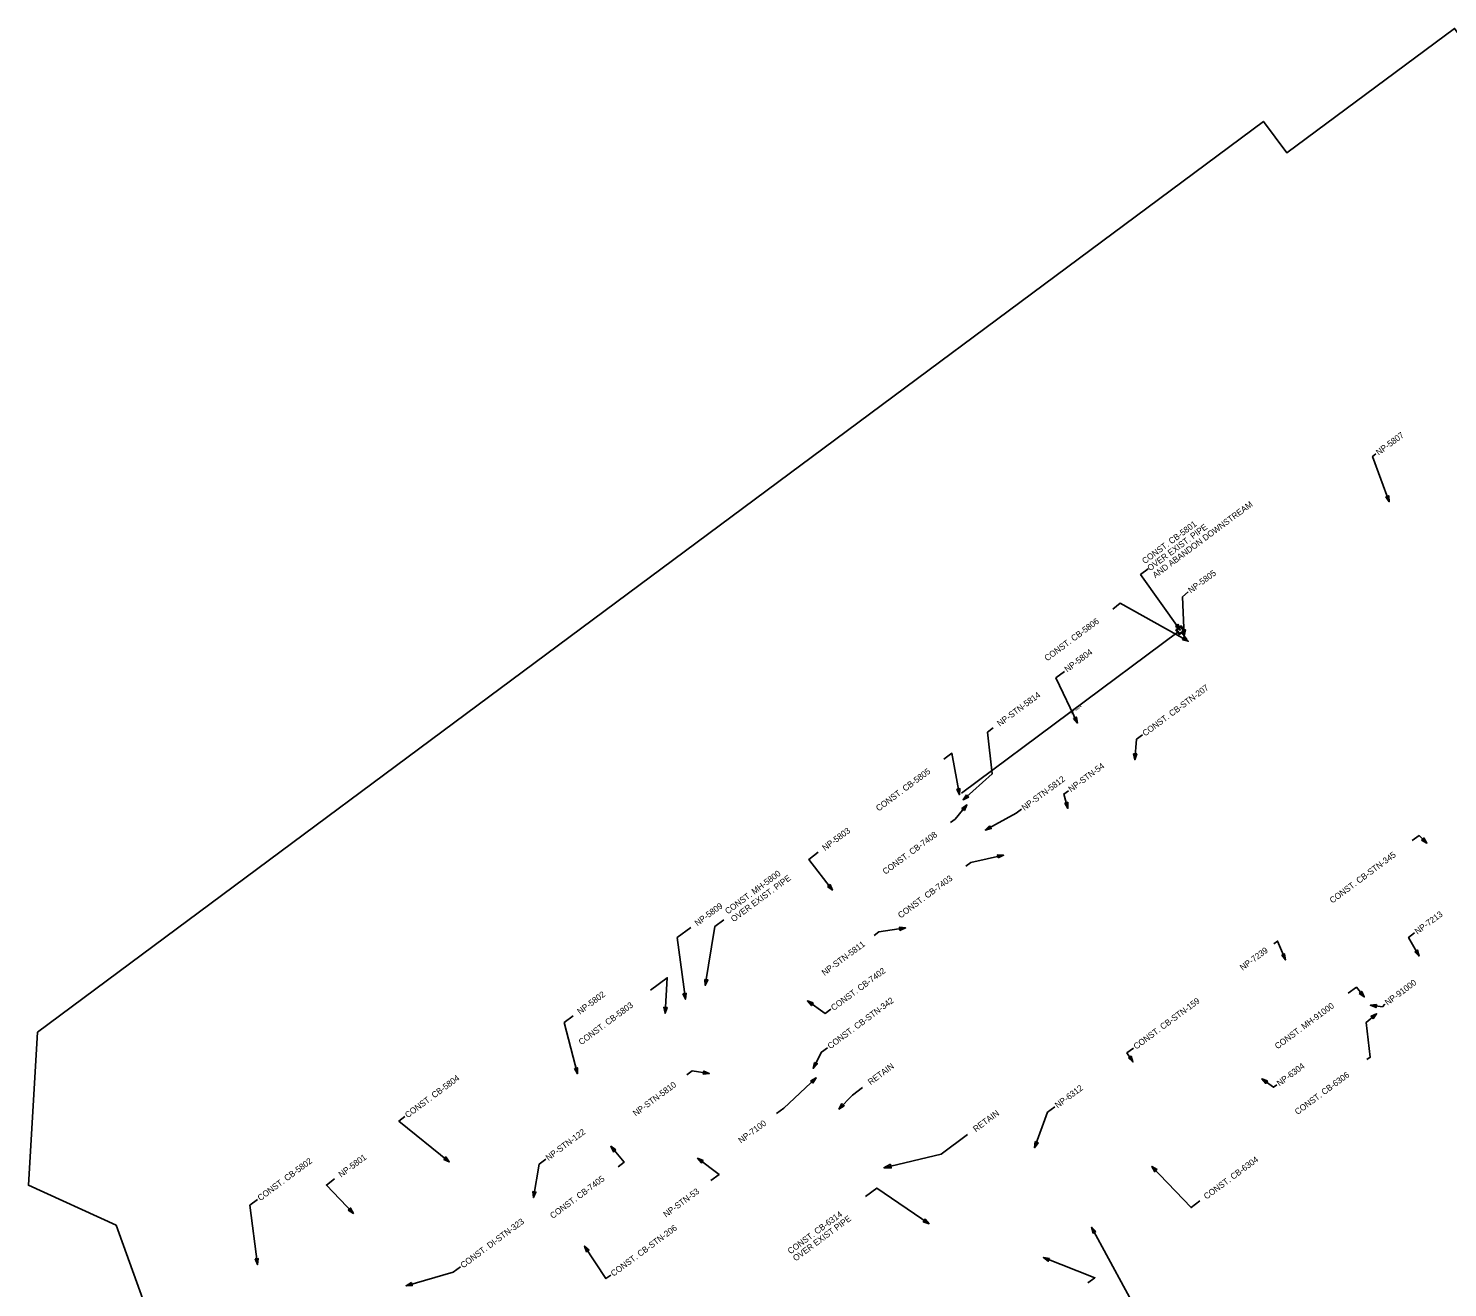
# Model space of a CAD drawing. Extents: x 1611197 to 1612945, y 1093889 to 1095652.
# Drawn here: x 1611197 to 1612358, y 1094591 to 1095622 of the extents above; entities that cross this region are included whole.
import ezdxf

# ---------------------------------------------------------------- set-up
doc = ezdxf.new("R2010")
doc.units = 0
for name, color, linetype in [('Default', 7, 'Continuous'), ('Plan_Clip', 7, 'Continuous'), ('RD_PD_DR_Inlet', 7, 'Continuous'), ('RD_PD_DR_Pipe', 7, 'Continuous'), ('RD_TX_Drainage', 7, 'Continuous')]:
    doc.layers.add(name, color=color, linetype=linetype)

msp = doc.modelspace()

# ---------------------------------------------------------------- linework, layer by layer
at = {"layer": 'Plan_Clip'}
msp.add_lwpolyline([(1611268.7, 1094642.2), (1611330.5, 1094471.1), (1611497.9, 1094245.9), (1611487.3, 1094233.1), (1611570.5, 1094184.4), (1611553.7, 1094158.9), (1611675.8, 1094087.5), (1611739.8, 1094059.2), (1612815.4, 1094815.5), (1612742.5, 1095078.7), (1612653.4, 1095198.5), (1612656.9, 1095201.1), (1612580.2, 1095304.3), (1612588.4, 1095320.1), (1612485.6, 1095458.4), (1612364.1, 1095621.9), (1612226.9, 1095519.9), (1612207.6, 1095545.8), (1611204.4, 1094800.1), (1611197, 1094674.8)], close=True, dxfattribs=at)
msp.add_lwpolyline([(1611268.7, 1094642.2), (1611330.5, 1094471.1), (1611497.9, 1094245.9), (1611487.3, 1094233.1), (1611570.5, 1094184.4), (1611553.7, 1094158.9), (1611675.8, 1094087.5), (1611739.8, 1094059.2), (1612815.4, 1094815.5), (1612742.5, 1095078.7), (1612653.4, 1095198.5), (1612656.9, 1095201.1), (1612580.2, 1095304.3), (1612588.4, 1095320.1), (1612485.6, 1095458.4), (1612364.1, 1095621.9), (1612226.9, 1095519.9), (1612207.6, 1095545.8), (1611204.4, 1094800.1), (1611197, 1094674.8)], close=True, dxfattribs=at)
msp.add_lwpolyline([(1611268.7, 1094642.2), (1611330.5, 1094471.1), (1611497.9, 1094245.9), (1611487.3, 1094233.1), (1611570.5, 1094184.4), (1611553.7, 1094158.9), (1611675.8, 1094087.5), (1611739.8, 1094059.2), (1612815.4, 1094815.5), (1612742.5, 1095078.7), (1612653.4, 1095198.5), (1612656.9, 1095201.1), (1612580.2, 1095304.3), (1612588.4, 1095320.1), (1612485.6, 1095458.4), (1612364.1, 1095621.9), (1612226.9, 1095519.9), (1612207.6, 1095545.8), (1611204.4, 1094800.1), (1611197, 1094674.8)], close=True, dxfattribs=at)
msp.add_lwpolyline([(1611268.7, 1094642.2), (1611330.5, 1094471.1), (1611497.9, 1094245.9), (1611487.3, 1094233.1), (1611570.5, 1094184.4), (1611553.7, 1094158.9), (1611675.8, 1094087.5), (1611739.8, 1094059.2), (1612815.4, 1094815.5), (1612742.5, 1095078.7), (1612653.4, 1095198.5), (1612656.9, 1095201.1), (1612580.2, 1095304.3), (1612588.4, 1095320.1), (1612485.6, 1095458.4), (1612364.1, 1095621.9), (1612226.9, 1095519.9), (1612207.6, 1095545.8), (1611204.4, 1094800.1), (1611197, 1094674.8)], close=True, dxfattribs=at)
msp.add_lwpolyline([(1611268.7, 1094642.2), (1611330.5, 1094471.1), (1611497.9, 1094245.9), (1611487.3, 1094233.1), (1611570.5, 1094184.4), (1611553.7, 1094158.9), (1611675.8, 1094087.5), (1611739.8, 1094059.2), (1612815.4, 1094815.5), (1612742.5, 1095078.7), (1612653.4, 1095198.5), (1612656.9, 1095201.1), (1612580.2, 1095304.3), (1612588.4, 1095320.1), (1612485.6, 1095458.4), (1612364.1, 1095621.9), (1612226.9, 1095519.9), (1612207.6, 1095545.8), (1611204.4, 1094800.1), (1611197, 1094674.8)], close=True, dxfattribs=at)
msp.add_lwpolyline([(1611268.7, 1094642.2), (1611330.5, 1094471.1), (1611497.9, 1094245.9), (1611487.3, 1094233.1), (1611570.5, 1094184.4), (1611553.7, 1094158.9), (1611675.8, 1094087.5), (1611739.8, 1094059.2), (1612815.4, 1094815.5), (1612742.5, 1095078.7), (1612653.4, 1095198.5), (1612656.9, 1095201.1), (1612580.2, 1095304.3), (1612588.4, 1095320.1), (1612485.6, 1095458.4), (1612364.1, 1095621.9), (1612226.9, 1095519.9), (1612207.6, 1095545.8), (1611204.4, 1094800.1), (1611197, 1094674.8)], close=True, dxfattribs=at)
msp.add_lwpolyline([(1611268.7, 1094642.2), (1611330.5, 1094471.1), (1611497.9, 1094245.9), (1611487.3, 1094233.1), (1611570.5, 1094184.4), (1611553.7, 1094158.9), (1611675.8, 1094087.5), (1611739.8, 1094059.2), (1612815.4, 1094815.5), (1612742.5, 1095078.7), (1612653.4, 1095198.5), (1612656.9, 1095201.1), (1612580.2, 1095304.3), (1612588.4, 1095320.1), (1612485.6, 1095458.4), (1612364.1, 1095621.9), (1612226.9, 1095519.9), (1612207.6, 1095545.8), (1611204.4, 1094800.1), (1611197, 1094674.8)], close=True, dxfattribs=at)
msp.add_lwpolyline([(1611268.7, 1094642.2), (1611330.5, 1094471.1), (1611497.9, 1094245.9), (1611487.3, 1094233.1), (1611570.5, 1094184.4), (1611553.7, 1094158.9), (1611675.8, 1094087.5), (1611739.8, 1094059.2), (1612815.4, 1094815.5), (1612742.5, 1095078.7), (1612653.4, 1095198.5), (1612656.9, 1095201.1), (1612580.2, 1095304.3), (1612588.4, 1095320.1), (1612485.6, 1095458.4), (1612364.1, 1095621.9), (1612226.9, 1095519.9), (1612207.6, 1095545.8), (1611204.4, 1094800.1), (1611197, 1094674.8)], close=True, dxfattribs=at)
at = {"layer": 'RD_PD_DR_Inlet'}
for p, q in [((1612137.9, 1095128), (1612137.9, 1095128)), ((1612138.3, 1095130.8), (1612138.3, 1095130.8)), ((1612138.3, 1095130.8), (1612138.3, 1095130.8)), ((1612139.5, 1095129.2), (1612139.5, 1095129.2)), ((1612139.5, 1095129.2), (1612139.5, 1095129.2)), ((1612140.7, 1095127.6), (1612140.7, 1095127.6)), ((1612140.7, 1095127.6), (1612140.7, 1095127.6)), ((1612141.1, 1095130.4), (1612141.1, 1095130.4))]:
    msp.add_line(p, q, dxfattribs=at)
for points in [[(1612135.9, 1095129.6), (1612138.8, 1095125.6), (1612143.2, 1095128.8), (1612140.2, 1095132.8)], [(1612140, 1095132), (1612136.7, 1095129.6), (1612139.1, 1095126.4), (1612142.3, 1095128.8)]]:
    msp.add_lwpolyline(points, close=True, dxfattribs=at)
at = {"layer": 'RD_PD_DR_Pipe'}
for p, q in [((1611960.5, 1094995.7), (1612137.9, 1095128)), ((1612140.7, 1095127.6), (1612145, 1095121.7))]:
    msp.add_line(p, q, dxfattribs=at)
at = {"layer": 'RD_TX_Drainage'}
for points in [[(1612299.7, 1095273.5), (1612297, 1095271.5), (1612310.6, 1095234.3)], [(1612113.4, 1095179.4), (1612107.1, 1095174.7), (1612139.5, 1095129.2)], [(1612146, 1095160.6), (1612141.5, 1095156.6), (1612142.8, 1095124.6)], [(1612084.3, 1095146.5), (1612090.5, 1095151.2), (1612146.1, 1095120.1)], [(1612044.9, 1095095.4), (1612037.9, 1095090.2), (1612055.5, 1095053.2)], [(1611986.5, 1095049.2), (1611981.9, 1095045.7), (1611985.7, 1095011.5), (1611961.9, 1094990.4)], [(1612108.6, 1095043.5), (1612103.8, 1095039.9), (1612102.3, 1095023.2)], [(1611946.2, 1095023.5), (1611952.7, 1095028.4), (1611958.9, 1094994.5)], [(1612048, 1094997.8), (1612044.3, 1094995), (1612047.6, 1094983.3)], [(1611951.7, 1094971.8), (1611955.4, 1094974.5), (1611965, 1094986.2)], [(1612009.8, 1094982.7), (1612005.3, 1094979.3), (1611980, 1094965.6)], [(1612329.4, 1094957), (1612335, 1094961.1), (1612341.5, 1094954.9)], [(1611843.4, 1094947.4), (1611835.7, 1094941.6), (1611854.9, 1094916.4)], [(1611964.2, 1094935.9), (1611968.3, 1094938.9), (1611995, 1094945)], [(1611766.2, 1094892.2), (1611758.8, 1094886.7), (1611750.9, 1094838.4)], [(1611739, 1094885.7), (1611728, 1094877.5), (1611734.6, 1094827)], [(1611889, 1094879.3), (1611892.9, 1094882.2), (1611914.8, 1094885.4)], [(1612331.4, 1094881.3), (1612326.4, 1094877.7), (1612335, 1094862.4)], [(1612216.2, 1094872.4), (1612219.2, 1094874.7), (1612225.6, 1094859.3)], [(1611706.1, 1094834.5), (1611719.8, 1094844.6), (1611718, 1094815.6)], [(1612276.9, 1094831.9), (1612283.7, 1094836.9), (1612290.1, 1094828.9)], [(1611853.7, 1094818.9), (1611849, 1094815.4), (1611834.5, 1094825.7)], [(1612307, 1094823.1), (1612305, 1094820.8), (1612295.2, 1094822.2)], [(1611642.9, 1094813.4), (1611635.5, 1094807.9), (1611646.2, 1094766)], [(1612292.4, 1094777.6), (1612295.1, 1094779.6), (1612291.8, 1094808.1), (1612300.3, 1094815.2)], [(1611850.9, 1094787.4), (1611846, 1094783.8), (1611839.3, 1094770.4)], [(1612101.3, 1094787.1), (1612096, 1094783.1), (1612100.9, 1094775.7)], [(1611735.8, 1094765.2), (1611740.2, 1094768.5), (1611754.1, 1094766.2)], [(1611809.2, 1094733.5), (1611815.2, 1094738), (1611841.7, 1094762.6)], [(1611879.6, 1094754.7), (1611871.3, 1094748.6), (1611860.3, 1094737.2)], [(1612218.5, 1094757), (1612215.9, 1094755), (1612206.4, 1094762)], [(1611505.1, 1094731), (1611500.2, 1094727.3), (1611541.4, 1094693.9)], [(1612037, 1094739), (1612030.9, 1094734.5), (1612020.4, 1094705.5)], [(1611679.5, 1094689.9), (1611684.5, 1094693.6), (1611673.7, 1094706.7)], [(1611965.6, 1094716.2), (1611943.9, 1094700.1), (1611897.1, 1094689.1)], [(1611620.3, 1094696), (1611615, 1094692.1), (1611610.2, 1094664.7)], [(1611755.5, 1094678.6), (1611762.2, 1094683.5), (1611744.6, 1094696.9)], [(1612155.6, 1094661.9), (1612148.4, 1094656.5), (1612116.4, 1094690.2)], [(1611447.5, 1094679.9), (1611440.9, 1094674.9), (1611463, 1094651.7)], [(1611882, 1094665.5), (1611891.3, 1094672.4), (1611934, 1094643.3)], [(1611384.5, 1094663.1), (1611378.3, 1094658.4), (1611384.5, 1094609.8)], [(1612096.1, 1094554.2), (1612108.7, 1094563.6), (1612067, 1094640.4)], [(1611673.5, 1094601.2), (1611669.6, 1094598.3), (1611652.1, 1094625)], [(1612064, 1094594.8), (1612069.8, 1094599.1), (1612027.6, 1094615.5)], [(1611550.5, 1094608), (1611544.7, 1094603.7), (1611506.1, 1094592.5)]]:
    msp.add_lwpolyline(points, dxfattribs=at)
for points in [[(1612307.8, 1095238.4), (1612310.6, 1095234.3), (1612310.2, 1095239.3)], [(1612135.7, 1095132.4), (1612139.5, 1095129.2), (1612137.8, 1095133.9)], [(1612141.3, 1095129.4), (1612142.8, 1095124.6), (1612143.9, 1095129.5)], [(1612141.3, 1095121.3), (1612146.1, 1095120.1), (1612142.5, 1095123.6)], [(1612052.3, 1095057), (1612055.5, 1095053.2), (1612054.6, 1095058.1)], [(1612101.4, 1095028.1), (1612102.3, 1095023.2), (1612104, 1095027.9)], [(1611956.7, 1094999), (1611958.9, 1094994.5), (1611959.3, 1094999.5)], [(1611962.9, 1094981.7), (1611965, 1094986.2), (1611960.9, 1094983.3)], [(1611964.7, 1094994.5), (1611961.9, 1094990.4), (1611966.4, 1094992.6)], [(1612045, 1094987.6), (1612047.6, 1094983.3), (1612047.5, 1094988.3)], [(1611983.6, 1094969.1), (1611980, 1094965.6), (1611984.9, 1094966.8)], [(1612337.1, 1094957.3), (1612341.5, 1094954.9), (1612338.9, 1094959.2)], [(1611990.6, 1094942.7), (1611995, 1094945), (1611990, 1094945.2)], [(1611850.9, 1094919.5), (1611854.9, 1094916.4), (1611853, 1094921)], [(1611910.2, 1094883.4), (1611914.8, 1094885.4), (1611909.8, 1094886)], [(1612331.5, 1094866), (1612335, 1094862.4), (1612333.7, 1094867.3)], [(1612222.6, 1094863.2), (1612225.6, 1094859.3), (1612225, 1094864.2)], [(1611750.4, 1094843.3), (1611750.9, 1094838.4), (1611753, 1094842.9)], [(1612286, 1094831.8), (1612290.1, 1094828.9), (1612288.1, 1094833.5)], [(1611732.6, 1094831.6), (1611734.6, 1094827), (1611735.2, 1094832)], [(1611839.2, 1094824), (1611834.5, 1094825.7), (1611837.7, 1094821.9)], [(1612300.2, 1094822.8), (1612295.2, 1094822.2), (1612299.8, 1094820.2)], [(1611717, 1094820.5), (1611718, 1094815.6), (1611719.6, 1094820.3)], [(1612297.4, 1094811.1), (1612300.3, 1094815.2), (1612295.8, 1094813.1)], [(1611840.3, 1094775.3), (1611839.3, 1094770.4), (1611842.6, 1094774.2)], [(1612097.1, 1094779), (1612100.9, 1094775.7), (1612099.3, 1094780.4)], [(1611643.8, 1094770.4), (1611646.2, 1094766), (1611646.3, 1094771)], [(1611749.1, 1094765.7), (1611754.1, 1094766.2), (1611749.6, 1094768.3)], [(1611839, 1094758.4), (1611841.7, 1094762.6), (1611837.3, 1094760.3)], [(1612211.1, 1094760.2), (1612206.4, 1094762), (1612209.5, 1094758.1)], [(1611862.7, 1094741.6), (1611860.3, 1094737.2), (1611864.6, 1094739.8)], [(1611677.7, 1094703.8), (1611673.7, 1094706.7), (1611675.7, 1094702.2)], [(1612020.9, 1094710.5), (1612020.4, 1094705.5), (1612023.3, 1094709.6)], [(1611536.9, 1094695.9), (1611541.4, 1094693.9), (1611538.5, 1094698)], [(1611749.3, 1094695), (1611744.6, 1094696.9), (1611747.7, 1094693)], [(1611902.4, 1094692), (1611897.1, 1094689.1), (1611903.1, 1094689)], [(1612120.6, 1094687.6), (1612116.4, 1094690.2), (1612118.7, 1094685.8)], [(1611609.8, 1094669.7), (1611610.2, 1094664.7), (1611612.3, 1094669.2)], [(1611458.7, 1094654.3), (1611463, 1094651.7), (1611460.6, 1094656.1)], [(1611929.3, 1094644.9), (1611934, 1094643.3), (1611930.8, 1094647.1)], [(1612070.5, 1094636.8), (1612067, 1094640.4), (1612068.2, 1094635.6)], [(1611655.9, 1094621.7), (1611652.1, 1094625), (1611653.7, 1094620.3)], [(1611382.6, 1094614.4), (1611384.5, 1094609.8), (1611385.1, 1094614.7)], [(1612032.5, 1094614.9), (1612027.6, 1094615.5), (1612031.6, 1094612.5)], [(1611510.4, 1094595.1), (1611506.1, 1094592.5), (1611511.1, 1094592.6)]]:
    msp.add_lwpolyline(points, close=True, dxfattribs=at)

# ---------------------------------------------------------------- texts
at = {"layer": 'Default'}
msp.add_text('NP-5804', height=2, rotation=36.7208, dxfattribs=at).set_placement((1612050.4, 1095060.2))
at = {"layer": 'RD_TX_Drainage'}
for s, rotation, p in [('NP-5807', 36.624, (1612302, 1095272.1)), ('AND ABANDON DOWNSTREAM', 36.624, (1612119.2, 1095171.6)), ('CONST. CB-5801', 36.624, (1612110.6, 1095183.2)), ('OVER EXIST. PIPE', 36.624, (1612114.9, 1095177.4)), ('NP-5805', 36.624, (1612148.3, 1095159.2)), ('CONST. CB-5806', 36.624, (1612030.7, 1095103.6)), ('NP-5804', 36.624, (1612047.1, 1095094.5)), ('NP-STN-5814', 36.624, (1611992, 1095050.1)), ('CONST. CB-STN-207', 36.624, (1612110.9, 1095042.1)), ('NP-STN-54', 36.624, (1612050.3, 1094996.4)), ('CONST. CB-5805', 36.624, (1611892.8, 1094980.7)), ('NP-STN-5812', 36.624, (1612012.1, 1094981.2)), ('NP-5803', 36.624, (1611848.9, 1094948.3)), ('CONST. CB-7408', 36.624, (1611898.3, 1094928.9)), ('CONST. CB-STN-345', 36.624, (1612264.1, 1094905.3)), ('CONST. MH-5800', 36.624, (1611769.3, 1094896.4)), ('OVER EXIST. PIPE', 36.624, (1611774.1, 1094890)), ('CONST. CB-7403', 36.624, (1611910.8, 1094893.1)), ('NP-5809', 36.624, (1611744.5, 1094886.7)), ('NP-7213', 36.624, (1612333.7, 1094879.9)), ('NP-STN-5811', 36.624, (1611848.5, 1094846.1)), ('NP-7239', 36.624, (1612190.7, 1094850.3)), ('CONST. CB-7402', 36.624, (1611856, 1094817.4)), ('NP-5802', 36.624, (1611648.4, 1094814.3)), ('NP-91000', 36.624, (1612309.3, 1094821.7)), ('CONST. CB-5803', 36.624, (1611649.5, 1094789.3)), ('CONST. CB-STN-342', 36.624, (1611853.2, 1094786)), ('CONST. CB-STN-159', 36.624, (1612103.6, 1094785.7)), ('CONST. MH-91000', 36.624, (1612219.2, 1094785.9)), ('RETAIN', 36.6256, (1611886.2, 1094756.6)), ('NP-6304', 36.624, (1612220.8, 1094755.6)), ('CONST. CB-5804', 36.624, (1611507.4, 1094729.6)), ('CONST. CB-6306', 36.624, (1612235.6, 1094732.2)), ('NP-STN-5810', 36.624, (1611694, 1094731)), ('NP-6312', 36.624, (1612039.3, 1094737.6)), ('NP-7100', 36.624, (1611780.2, 1094708.8)), ('RETAIN', 36.6256, (1611972.3, 1094718.1)), ('NP-STN-122', 36.624, (1611622.6, 1094694.6)), ('CONST. CB-5802', 36.624, (1611386.8, 1094661.7)), ('NP-5801', 36.624, (1611453, 1094680.9)), ('CONST. CB-6304', 36.624, (1612161.1, 1094662.9)), ('CONST. CB-7405', 36.624, (1611626.1, 1094647.1)), ('NP-STN-53', 36.624, (1611718.8, 1094648.2)), ('CONST. DI-STN-323', 36.624, (1611552.8, 1094606.6)), ('CONST. CB-6314', 36.624, (1611820.6, 1094618.1)), ('OVER EXIST PIPE', 36.624, (1611824.9, 1094612.3)), ('CONST. CB-STN-206', 36.624, (1611675.8, 1094599.8))]:
    msp.add_text(s, height=5, rotation=rotation, dxfattribs=at).set_placement(p)

doc.saveas('drawing.dxf')
